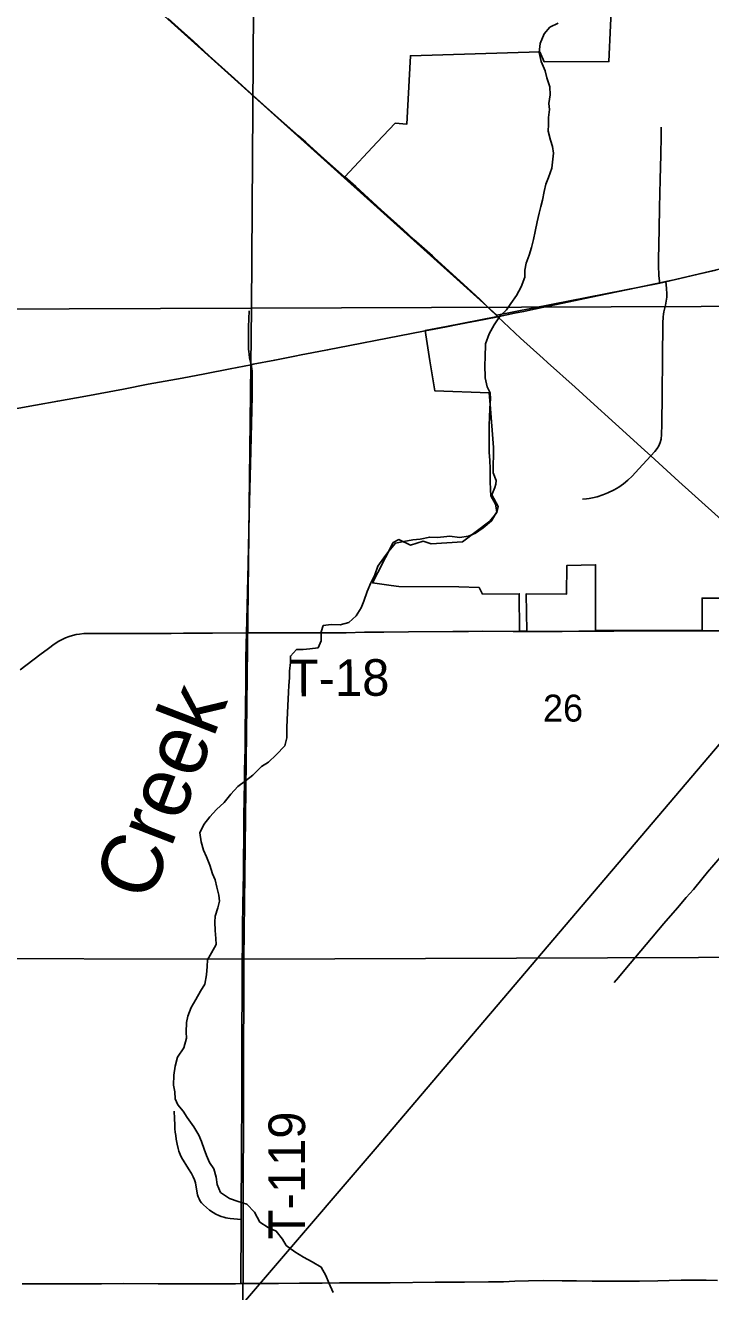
# Model space of a CAD drawing. Extents: x 0 to 34, y 0 to 22.
# Drawn here: x 2.532 to 3.064, y 14.978 to 15.961 of the extents above; entities that cross this region are included whole.
import ezdxf

# ---------------------------------------------------------------- set-up
doc = ezdxf.new("R2010")
doc.units = 0
for name, color, linetype in [('GM_X_City_Street', 7, 'Continuous'), ('GM_X_Corporation', 7, 'Continuous'), ('GM_X_County_Road', 7, 'Continuous'), ('GM_X_Minor_River', 7, 'Continuous'), ('GM_X_Minor_River_Text', 7, 'Continuous'), ('GM_X_Rail_Line', 7, 'Continuous'), ('GM_X_Section_Text', 7, 'Continuous'), ('GM_X_State_Route', 7, 'Continuous'), ('GM_X_Township_Road', 7, 'Continuous'), ('GM_X_Township_Road_Text', 7, 'Continuous'), ('GM_X_US_Route', 7, 'Continuous')]:
    doc.layers.add(name, color=color, linetype=linetype)

msp = doc.modelspace()

# ---------------------------------------------------------------- linework, layer by layer
at = {"layer": 'GM_X_City_Street'}
for points in [[(3.0245, 15.76103), (3.02435, 15.76244), (3.02389, 15.76674), (3.02373, 15.76885), (3.02352, 15.77254), (3.02344, 15.77533), (3.02351, 15.7791), (3.02409, 15.80269), (3.02439, 15.81951), (3.02481, 15.84127), (3.02535, 15.86053), (3.02563, 15.87484), (3.02569, 15.88199)], [(3.01766, 15.6267), (3.0207, 15.63005), (3.02254, 15.63236), (3.02369, 15.63443), (3.02484, 15.63716), (3.02552, 15.63974), (3.02593, 15.64333), (3.0261, 15.65104), (3.02638, 15.67466), (3.02668, 15.70263), (3.02695, 15.72969), (3.02722, 15.73471), (3.02745, 15.73666), (3.02777, 15.73848), (3.02892, 15.74367), (3.02956, 15.74681), (3.02997, 15.74986), (3.0301, 15.75257), (3.02978, 15.75659), (3.02922, 15.76201)], [(2.9646, 15.59307), (2.96751, 15.59333), (2.96964, 15.59366), (2.97227, 15.59418), (2.97597, 15.59505), (2.98019, 15.59639), (2.98429, 15.59801), (2.98912, 15.60033), (2.99268, 15.6024), (2.9963, 15.60496), (2.9997, 15.60778), (3.0031, 15.61105), (3.0082, 15.61657), (3.01766, 15.6267)]]:
    msp.add_lwpolyline(points, dxfattribs=at)
at = {"layer": 'GM_X_Corporation'}
for points in [[(2.21995, 16.24572), (2.71086, 16.24467), (2.70763, 15.74147), (2.21216, 15.73952)], [(2.71086, 16.24467), (3.20823, 16.24661), (3.19629, 15.74328), (2.70763, 15.74147)], [(2.70763, 15.74147), (2.70155, 15.23601), (2.20515, 15.23711), (2.21216, 15.73952)], [(3.19629, 15.74328), (3.19551, 15.23797), (2.70155, 15.23601), (2.70763, 15.74147)], [(2.20515, 15.23711), (2.70155, 15.23601), (2.70022, 14.73337), (2.69643, 14.7334), (2.21255, 14.73573), (2.19853, 14.73564)], [(2.70155, 15.23601), (3.19551, 15.23797), (3.19987, 14.73736), (3.19438, 14.73721), (2.70022, 14.73337)]]:
    msp.add_lwpolyline(points, close=True, dxfattribs=at)
msp.add_lwpolyline([(3.0742, 15.51618), (3.05733, 15.51633), (3.0573, 15.49132), (3.03605, 15.4913), (3.00531, 15.49119), (2.97458, 15.49108), (2.97471, 15.54226), (2.95244, 15.54172), (2.95211, 15.51943), (2.92091, 15.51978), (2.92124, 15.4907), (2.91569, 15.49067), (2.91545, 15.51977), (2.887, 15.51952), (2.88422, 15.52456), (2.86863, 15.52502), (2.82199, 15.52536), (2.81596, 15.52618), (2.80153, 15.52814), (2.80562, 15.53617), (2.81748, 15.55946), (2.82184, 15.56183), (2.83091, 15.55751), (2.84074, 15.56052), (2.84696, 15.55849), (2.87146, 15.56), (2.89253, 15.57598), (2.89796, 15.58281), (2.89899, 15.58746), (2.8942, 15.59654), (2.89635, 15.60225), (2.89714, 15.60468), (2.89743, 15.60774), (2.89527, 15.61365), (2.89536, 15.63328), (2.8929, 15.66666), (2.89201, 15.67561), (2.892, 15.67571), (2.84979, 15.67723), (2.84606, 15.70062), (2.84232, 15.72402), (2.85892, 15.72723), (2.89862, 15.73502), (2.88476, 15.74843), (2.86926, 15.76252), (2.8496, 15.78053), (2.84799, 15.78196), (2.8336, 15.79479), (2.82524, 15.80256), (2.80834, 15.81773), (2.78856, 15.83574), (2.77994, 15.84343), (2.80519, 15.87018), (2.8192, 15.88503), (2.82827, 15.88429), (2.82875, 15.89406), (2.8309, 15.93731), (2.93146, 15.94033), (2.93482, 15.93262), (2.98499, 15.93273), (2.98743, 15.98906)], dxfattribs=at)
at = {"layer": 'GM_X_County_Road'}
for points in [[(2.70365, 15.48952), (2.70388, 15.49919), (2.70491, 15.5433), (2.7058, 15.58134), (2.70696, 15.63056), (2.70796, 15.6732), (2.708, 15.69095), (2.70796, 15.69278), (2.70782, 15.69435), (2.7076, 15.69603), (2.70719, 15.69751)], [(2.52811, 15.46069), (2.54319, 15.47219), (2.54989, 15.47723), (2.55442, 15.48048), (2.55805, 15.48283), (2.56101, 15.48448), (2.56323, 15.48552), (2.56609, 15.48663), (2.56873, 15.48743), (2.57143, 15.48805), (2.57416, 15.48848), (2.57754, 15.48878), (2.58248, 15.48896), (2.59179, 15.489), (2.61106, 15.48888), (2.62256, 15.48883), (2.63655, 15.48895), (2.64525, 15.48895), (2.65488, 15.48902), (2.66607, 15.48905), (2.67726, 15.48907), (2.70365, 15.48952)], [(2.98906, 15.218), (2.99233, 15.22194), (2.99731, 15.2279), (3.01403, 15.24754), (3.02757, 15.26375), (3.0382, 15.27591), (3.04504, 15.28396), (3.05055, 15.29028), (3.05704, 15.29823), (3.06164, 15.30369), (3.07131, 15.31504)], [(2.52955, 14.98417), (2.56374, 14.98414), (2.58207, 14.9842), (2.59108, 14.98422), (2.60818, 14.98427), (2.63522, 14.9842), (2.64921, 14.9842), (2.65915, 14.98413), (2.67251, 14.98412), (2.69519, 14.98421), (2.69942, 14.98424)], [(2.69942, 14.98424), (2.71291, 14.98432), (2.71842, 14.98438)], [(2.71842, 14.98438), (2.72844, 14.98449), (2.74492, 14.98459), (2.76232, 14.98471), (2.77591, 14.98479)], [(2.77591, 14.98479), (2.78345, 14.98483), (2.81515, 14.98485), (2.85027, 14.98533), (2.87295, 14.98543), (2.89159, 14.98565), (2.90309, 14.98578), (2.91208, 14.98609), (2.92265, 14.98655), (2.93416, 14.98667), (2.94877, 14.98648), (2.95996, 14.98632), (2.97207, 14.98605), (2.99009, 14.98611), (3.00873, 14.9863), (3.02302, 14.98652), (3.03167, 14.98671), (3.04098, 14.98706), (3.0472, 14.98704), (3.06057, 14.98685), (3.06927, 14.98674)]]:
    msp.add_lwpolyline(points, dxfattribs=at)
at = {"layer": 'GM_X_Minor_River'}
for points in [[(2.94554, 15.96253), (2.93926, 15.95954), (2.93467, 15.95426), (2.93158, 15.94689), (2.93096, 15.93987), (2.93242, 15.93284), (2.9356, 15.92561), (2.9367, 15.92009), (2.93911, 15.91325), (2.93945, 15.90698), (2.93845, 15.90035), (2.9388, 15.8956), (2.93818, 15.88934), (2.93814, 15.88403), (2.93791, 15.87872), (2.93957, 15.87169), (2.94124, 15.86693), (2.94196, 15.86161), (2.94135, 15.85479), (2.94074, 15.85005), (2.93822, 15.84286), (2.9361, 15.83756), (2.93473, 15.83207), (2.93354, 15.82525), (2.93218, 15.82032), (2.93081, 15.81502), (2.92925, 15.80839), (2.92787, 15.801), (2.92649, 15.79456), (2.92493, 15.7885), (2.92299, 15.78244), (2.92086, 15.77639), (2.91987, 15.77089), (2.91964, 15.76539), (2.91693, 15.75782), (2.91328, 15.75121), (2.90887, 15.74498), (2.90542, 15.74007)], [(2.90542, 15.74007), (2.90064, 15.73536), (2.89603, 15.72838), (2.892, 15.72158), (2.8891, 15.71382), (2.88902, 15.703), (2.8886, 15.6975), (2.88891, 15.68725), (2.89057, 15.68041), (2.89281, 15.67565), (2.89315, 15.6709), (2.89253, 15.6637), (2.89229, 15.6563), (2.89206, 15.65118), (2.89202, 15.64587), (2.89218, 15.64093), (2.89194, 15.63486), (2.89209, 15.62955), (2.89262, 15.62309), (2.89295, 15.61702), (2.89288, 15.60715), (2.89302, 15.60051), (2.89337, 15.59576), (2.89693, 15.58929), (2.89802, 15.5834), (2.89398, 15.57622), (2.8875, 15.57095), (2.88139, 15.56663), (2.87606, 15.5644), (2.86904, 15.5635), (2.86164, 15.56431), (2.8569, 15.56397), (2.85177, 15.56344), (2.84589, 15.56367), (2.83848, 15.56221), (2.83278, 15.56149), (2.82575, 15.56022), (2.81929, 15.55894), (2.81394, 15.55253), (2.81029, 15.54762), (2.80569, 15.54102), (2.80318, 15.53439), (2.80029, 15.52815), (2.79739, 15.52153), (2.79468, 15.51396), (2.79275, 15.50886), (2.78872, 15.50262), (2.78318, 15.49735), (2.77634, 15.4957), (2.76951, 15.49575), (2.76324, 15.49503), (2.76169, 15.49011), (2.76164, 15.48309), (2.75932, 15.4778), (2.75286, 15.4769), (2.74755, 15.47656), (2.74243, 15.47641), (2.73783, 15.47132), (2.7378, 15.46638), (2.73718, 15.45975), (2.73695, 15.45444), (2.73653, 15.44856), (2.7363, 15.44344), (2.73607, 15.43793), (2.73566, 15.433), (2.73543, 15.42693), (2.7352, 15.42219), (2.73496, 15.41574), (2.73491, 15.40797), (2.73354, 15.40171), (2.72684, 15.39474), (2.72073, 15.38891), (2.71539, 15.38553), (2.70852, 15.37894), (2.70298, 15.37462), (2.69707, 15.37011), (2.69152, 15.36408), (2.68635, 15.35767), (2.68043, 15.35221), (2.67527, 15.34655), (2.67067, 15.34052), (2.6674, 15.33409), (2.66849, 15.32725), (2.67034, 15.3206), (2.67258, 15.31546), (2.67519, 15.30918), (2.67741, 15.30233), (2.67928, 15.29757), (2.68056, 15.29187), (2.68223, 15.28579), (2.68276, 15.28104), (2.6814, 15.27592), (2.67926, 15.26949), (2.67923, 15.26475), (2.67937, 15.25829), (2.6799, 15.25222), (2.68005, 15.24747), (2.6764, 15.24105), (2.67352, 15.23557), (2.6731, 15.23045), (2.67267, 15.224)], [(2.67267, 15.224), (2.67129, 15.2168), (2.66803, 15.21132), (2.66438, 15.2049), (2.66073, 15.19866), (2.65821, 15.19185), (2.65704, 15.18693), (2.65698, 15.17953), (2.65714, 15.17478), (2.655, 15.16721), (2.65001, 15.16004), (2.64825, 15.15303), (2.64725, 15.14602), (2.64701, 15.13824), (2.64811, 15.13311), (2.64826, 15.12779), (2.65031, 15.12304), (2.65445, 15.11807), (2.65764, 15.11311), (2.66271, 15.10587), (2.66665, 15.09957), (2.6687, 15.09463), (2.67074, 15.08854), (2.6726, 15.08359), (2.67484, 15.07826), (2.67822, 15.07349), (2.68026, 15.06684), (2.68098, 15.06133), (2.68359, 15.05505), (2.69058, 15.05044), (2.6972, 15.04793), (2.70402, 15.04598), (2.70986, 15.03986), (2.71397, 15.03205), (2.72039, 15.02783), (2.72682, 15.02494), (2.73152, 15.01883), (2.73452, 15.01388), (2.74112, 15.00889), (2.74793, 15.00486), (2.75473, 15.0012), (2.76172, 14.99716), (2.76528, 14.9905), (2.76751, 14.98479), (2.77106, 14.97736)]]:
    msp.add_lwpolyline(points, dxfattribs=at)
at = {"layer": 'GM_X_Rail_Line'}
for points in [[(3.87267, 15.94556), (3.81111, 15.93714), (3.73847, 15.94326), (3.60197, 15.91725), (3.48115, 15.89698), (3.42495, 15.8507), (3.18526, 15.79853), (3.02464, 15.76082), (2.89809, 15.73596), (2.60407, 16.00063), (2.47782, 16.11184), (2.33987, 16.24504), (2.23167, 16.2458), (2.21504, 16.26646), (2.14289, 16.38363), (2.11165, 16.43175), (2.10072, 16.44113), (2.1, 16.44138)], [(2.1, 14.2793), (2.17615, 14.36566), (2.49842, 14.73281), (2.80361, 15.08859), (3.07649, 15.40969), (3.30023, 15.67247), (3.32247, 15.69248), (3.34849, 15.71089), (3.38277, 15.73382), (3.4199, 15.75012), (3.47025, 15.76679), (3.52412, 15.78019), (3.64176, 15.80886), (3.72472, 15.82815), (3.7597, 15.83673), (3.78011, 15.84488), (3.80172, 15.85717), (3.81743, 15.87046), (3.87267, 15.94556)]]:
    msp.add_lwpolyline(points, dxfattribs=at)
at = {"layer": 'GM_X_State_Route'}
for points in [[(2.64296, 15.96628), (2.65336, 15.95686), (2.66225, 15.94881), (2.67471, 15.93721), (2.69434, 15.91954), (2.70617, 15.90885), (2.71673, 15.89934), (2.72378, 15.89302), (2.73287, 15.88501), (2.74398, 15.8751), (2.74964, 15.87011), (2.76144, 15.85959), (2.77514, 15.84755), (2.78005, 15.84316)], [(2.78005, 15.84316), (2.78867, 15.83546), (2.80845, 15.81745), (2.81874, 15.80822)], [(2.81874, 15.80822), (2.82536, 15.80229), (2.83371, 15.79452), (2.84971, 15.78025), (2.86937, 15.76225), (2.86975, 15.76191)], [(2.91293, 15.73764), (2.91902, 15.73892), (2.92833, 15.74086), (2.95427, 15.74639), (2.97617, 15.75094), (3.00736, 15.75742), (3.0245, 15.76103), (3.02922, 15.76201), (3.03568, 15.76344), (3.05418, 15.76767), (3.06808, 15.77091)], [(2.86975, 15.76191), (2.88487, 15.74815), (2.89873, 15.73474)], [(2.89873, 15.73474), (2.90684, 15.73635), (2.91293, 15.73764)]]:
    msp.add_lwpolyline(points, dxfattribs=at)
at = {"layer": 'GM_X_Township_Road'}
msp.add_line((2.9158, 15.4904), (2.92135, 15.49042), dxfattribs=at)
for points in [[(2.70719, 15.69751), (2.70613, 15.70286), (2.70571, 15.70557), (2.70551, 15.70785), (2.70537, 15.70957), (2.70527, 15.71131), (2.70513, 15.71371), (2.70512, 15.71632), (2.70533, 15.72694), (2.70587, 15.7394)], [(3.05792, 15.49105), (3.06147, 15.49105), (3.08198, 15.49107), (3.10031, 15.49115), (3.11646, 15.4912), (3.12703, 15.49124), (3.12954, 15.49131), (3.13206, 15.49161), (3.13425, 15.49211), (3.13605, 15.49279), (3.13772, 15.49376), (3.13922, 15.49496), (3.14102, 15.49673), (3.1471, 15.50342), (3.1502, 15.50682)], [(2.70365, 15.48952), (2.72324, 15.48948), (2.76195, 15.48931), (2.78097, 15.48948), (2.79519, 15.48995), (2.81039, 15.48998), (2.82934, 15.49024), (2.86383, 15.49049), (2.87594, 15.49054), (2.88678, 15.49062), (2.91067, 15.49038), (2.9158, 15.4904)], [(2.92135, 15.49042), (2.94882, 15.49055), (2.96179, 15.49059), (2.9746, 15.49074)], [(2.9746, 15.49074), (2.97883, 15.49079), (2.98877, 15.49078), (3.00338, 15.49082), (3.02885, 15.49102), (3.05742, 15.49105), (3.05792, 15.49105)], [(2.69948, 15.03395), (2.69946, 15.03778), (2.69944, 15.0423), (2.69952, 15.05629), (2.69968, 15.06841), (2.6997, 15.08426), (2.69983, 15.10042), (2.69997, 15.11658), (2.69999, 15.13181), (2.70002, 15.13989), (2.70004, 15.14579), (2.70008, 15.15355), (2.70012, 15.15946), (2.7001, 15.1638), (2.70011, 15.17903), (2.70019, 15.19115), (2.70022, 15.19923), (2.70028, 15.20295), (2.70036, 15.21442), (2.70034, 15.22155), (2.70036, 15.23024), (2.70041, 15.23831), (2.70049, 15.24359), (2.70054, 15.24949), (2.70055, 15.25633), (2.70062, 15.26348), (2.7009, 15.27653), (2.70114, 15.29301), (2.70127, 15.30015), (2.70138, 15.30916), (2.70145, 15.31724), (2.70148, 15.31941), (2.70154, 15.3247), (2.70157, 15.32842), (2.70164, 15.33619), (2.70172, 15.34582), (2.70188, 15.36167), (2.70205, 15.37224), (2.70222, 15.38249), (2.70254, 15.39958), (2.70278, 15.41325), (2.70324, 15.44992), (2.7033, 15.4692), (2.70348, 15.48039), (2.70365, 15.48952)], [(2.69948, 15.03395), (2.69381, 15.0346), (2.691, 15.03492), (2.68914, 15.03516), (2.68752, 15.03545), (2.68609, 15.03578), (2.6841, 15.03645), (2.68219, 15.03725), (2.67989, 15.0383), (2.67769, 15.03956), (2.67509, 15.04132), (2.67263, 15.04328), (2.67029, 15.04537), (2.66878, 15.04701), (2.66782, 15.0483), (2.66687, 15.04996), (2.66609, 15.05172), (2.66565, 15.05328), (2.66468, 15.05911), (2.66401, 15.06243), (2.66329, 15.06477), (2.66239, 15.06704), (2.66098, 15.06977), (2.65876, 15.07349), (2.65335, 15.08223), (2.65221, 15.08448), (2.65117, 15.08713), (2.65052, 15.08924), (2.6498, 15.09247), (2.64918, 15.09628), (2.64875, 15.09933), (2.64842, 15.10185), (2.64818, 15.10432), (2.64804, 15.10747), (2.64786, 15.11248), (2.64764, 15.11802)], [(2.69942, 14.98424), (2.69937, 14.98821), (2.69924, 14.99786), (2.69943, 15.01868), (2.69944, 15.02583), (2.69946, 15.02969), (2.69948, 15.03395)]]:
    msp.add_lwpolyline(points, dxfattribs=at)
at = {"layer": 'GM_X_US_Route'}
for p, q in [((2.88828, 15.73271), (2.89873, 15.73474)), ((2.84243, 15.72374), (2.84927, 15.72506))]:
    msp.add_line(p, q, dxfattribs=at)
for points in [[(2.84927, 15.72506), (2.85903, 15.72696), (2.86909, 15.72892), (2.8828, 15.73164), (2.88828, 15.73271)], [(2.89873, 15.73474), (2.91651, 15.71818), (2.93407, 15.70221)], [(2.74611, 15.70509), (2.75438, 15.70666), (2.76659, 15.70895), (2.78397, 15.7124), (2.81325, 15.71816), (2.84102, 15.72347), (2.84243, 15.72374)], [(2.47788, 15.65503), (2.53998, 15.66623), (2.55712, 15.66929), (2.57885, 15.6731), (2.60817, 15.67859), (2.6274, 15.68231), (2.65368, 15.68715), (2.6714, 15.69047), (2.69094, 15.69419), (2.70719, 15.69751)], [(2.70719, 15.69751), (2.7089, 15.69786), (2.72568, 15.70115), (2.74125, 15.70416), (2.74611, 15.70509)], [(2.93407, 15.70221), (2.93743, 15.69915), (2.9587, 15.68004), (2.97076, 15.66927), (2.99003, 15.65166), (3.01267, 15.63128), (3.01766, 15.6267), (3.03929, 15.60696), (3.04947, 15.59782), (3.07493, 15.57483), (3.08153, 15.56887), (3.09703, 15.55495), (3.10672, 15.5462), (3.11727, 15.53655), (3.12718, 15.52758), (3.13637, 15.51921), (3.1502, 15.50682)]]:
    msp.add_lwpolyline(points, dxfattribs=at)

# ---------------------------------------------------------------- texts
at = {"layer": 'GM_X_Minor_River_Text'}
msp.add_text('Creek', height=0.047373, rotation=68.89261, dxfattribs=at).set_placement((2.62856, 15.27915))
at = {"layer": 'GM_X_Section_Text'}
msp.add_text('26', height=0.020928, rotation=0.00001, dxfattribs=at).set_placement((2.93382, 15.4205))
at = {"layer": 'GM_X_Township_Road_Text'}
for s, rotation, p in [('T-18', 0.3528, (2.73657, 15.44012)), ('T-119', 90, (2.74917, 15.0186))]:
    msp.add_text(s, height=0.028409, rotation=rotation, dxfattribs=at).set_placement(p)

doc.saveas('drawing.dxf')
